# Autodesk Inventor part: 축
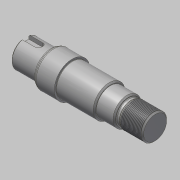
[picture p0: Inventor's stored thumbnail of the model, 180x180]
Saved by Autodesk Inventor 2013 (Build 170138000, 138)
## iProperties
Created: 2019-05
Part Number: 축
Material: 강철, 연강
Document SubType Name: Modeling
Designer: mduedu
Density: 1 g/cm^3
Author: mduedu
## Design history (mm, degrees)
sketch "스케치1"
  geometry: L1 (0, 0)-(20, 0); L2 (20, 0)-(20, 11); L3 (20, 11)-(0, 11); L4 (0, 11)-(0, 0); L5 (20, 0)-(37, 0); L6 (37, 0)-(37, 14); L7 (37, 14)-(20, 14); L8 (20, 14)-(20, 0); L9 (37, 0)-(67, 0); L10 (67, 0)-(67, 12.5); L11 (67, 12.5)-(37, 12.5); L12 (37, 12.5)-(37, 0); L13 (67, 0)-(81, 0); L14 (81, 0)-(81, 11); L15 (81, 11)-(67, 11); L16 (67, 11)-(67, 0); L17 (81, 0)-(102, 0); L18 (102, 0)-(102, 10); L19 (102, 10)-(81, 10); L20 (81, 10)-(81, 0)
  constraints: 40 end point, 10 parallel, 5 horizontal, 5 perpendicular
  dimensions: "d0" = 102 distance between parallel lines of L18 L4; "d2" = 21 distance of L18.end L19.end; "d3" = 14 distance of L14.end L15.end; "d4" = 30 distance of L10.end L11.end; "d5" = 17 distance of L6.end L7.end; "d6" = 22 diameter of L3 L1; "d7" = 28 diameter of L7 L5; "d8" = 25 diameter of L11 L9; "d9" = 22 diameter of L15 L13; "d10" = 20 diameter of L19 L17
revolve "회전1" sketch "스케치1" stored, may be unused: angle "d11" = 90 deg
chamfer "모따기1" distance "d12" = 2.34; stored, may be unused: second distance "d13" = 2, angle "d14" = 30 deg
fillet "모깎기1" dims "d15" = 2, "d16" = 1
fillet "모깎기2" dims "d17" = 0.3
chamfer "모따기2" distance "d18" = 1; stored, may be unused: second distance "d19" = 2, angle "d20" = 30 deg
sketch "스케치2"
  geometry: L1 (102, -10)-(81, -10) reference; L2 (81, -10)-(81, -11) reference; L3 (81, -11)-(67, -11) reference; L4 (67, -11)-(67, -11.5) reference; L5 (67, -11.5)-(66, -12.5) reference; L6 (66, -12.5)-(37.3, -12.5) reference; L7 (37, -12.8)-(37, -14) reference; L8 (37, -14)-(22.876, -14) reference; L9 (21.876, -13.732)-(20.5, -12.938) reference; L10 (20, -12.072)-(20, -11) reference; L11 (20, -11)-(0, -11) reference; L12 (0, -11)-(0, 11) reference; L13 (0, 11)-(20, 11) reference; L14 (20, 11)-(20, 12.072) reference; L15 (20.5, 12.938)-(21.876, 13.732) reference; L16 (22.876, 14)-(37, 14) reference; L17 (37, 14)-(37, 12.8) reference; L18 (37.3, 12.5)-(66, 12.5) reference; L19 (66, 12.5)-(67, 11.5) reference; L20 (67, 11.5)-(67, 11) reference; L21 (67, 11)-(81, 11) reference; L22 (81, 11)-(81, 10) reference; L23 (81, 10)-(102, 10) reference; L24 (102, 10)-(102, -10) reference; L25 (0, 0)-(102, 0); L26 (81, 10)-(84.726, 10); L27 (83.34, 9.2)-(81, 9.2); L28 (81, 9.2)-(81, 10); L29 (84.726, 10)-(83.34, 9.2); A1 r 0.3 centre (37.3, -12.8) between (37.3, -12.5) and (37, -12.8) reference; A2 r 2 centre (22.876, -12) between (21.876, -13.732) and (22.876, -14) reference; A3 r 1 centre (21, -12.072) between (20, -12.072) and (20.5, -12.938) reference; A4 r 1 centre (21, 12.072) between (20.5, 12.938) and (20, 12.072) reference; A5 r 2 centre (22.876, 12) between (22.876, 14) and (21.876, 13.732) reference; A6 r 0.3 centre (37.3, 12.8) between (37, 12.8) and (37.3, 12.5) reference
  constraints: 10 end point, 1 horizontal, 1 midpoint, 1 parallel, 1 vertical
  dimensions: "d21" = 18.4 diameter of L27 L25; "d23" = 2.34 distance of L27.start L27.end; "d24" = 30 deg angle of L23 L29
revolve "회전2" sketch "스케치2" stored, may be unused: angle "d25" = 90 deg
fillet "모깎기3" dims "d26" = 0.6
chamfer "모따기3" distance "d27" = 1; stored, may be unused: second distance "d28" = 2, angle "d29" = 30 deg
feature "스레드1" dims "d30" = 10, "d31" = 0
chamfer "모따기4" distance "d32" = 1; stored, may be unused: second distance "d33" = 2, angle "d34" = 30 deg
node "작업 평면1"
sketch "스케치3"
  geometry: L1 (10, -3)-(-1, -3); L2 (-1, -3)-(-1, 3); L3 (-1, 3)-(10, 3); L4 (10, 3)-(10, -3); 3 further points
  constraints: 8 end point, 2 midpoint, 2 parallel, 1 coincident, 1 horizontal, 1 perpendicular, 1 vertical alignment, 2 other
  dimensions: "d35" = 14 dimension on L4; "d37" = 6 distance between parallel lines of L3 L1
extrude "돌출1" cut sketch "스케치3" distance "d38" = 3.5; taper "d39" = 0 deg
chamfer "모따기5" distance "d40" = 1; stored, may be unused: second distance "d41" = 2, angle "d42" = 30 deg
node "솔리드1"
node "절단 모서리 투영1"
